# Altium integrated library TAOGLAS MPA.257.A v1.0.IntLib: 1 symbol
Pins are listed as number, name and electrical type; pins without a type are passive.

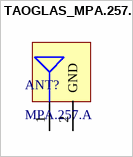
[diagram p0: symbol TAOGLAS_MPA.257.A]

## TAOGLAS_MPA.257.A
designator ANT?, comment MPA.257.A
WiFi Tri-Band 2.4/5.8/7.125GHz SMD Stamp Metal PIFA Antenna, 24*5.4*4.9mm; ComponentLibStatus: Created; MFG: Taoglas; Temp_High: +85C; Temp_Low: -40C
footprint TAOGLAS_MPA.257.A (WiFi Tri-Band 2.4/5.8/7.125GHz SMD Stamp Metal PIFA Antenna, 24*5.4*4.9mm)
pins: 1 RF FEED, 2 GND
